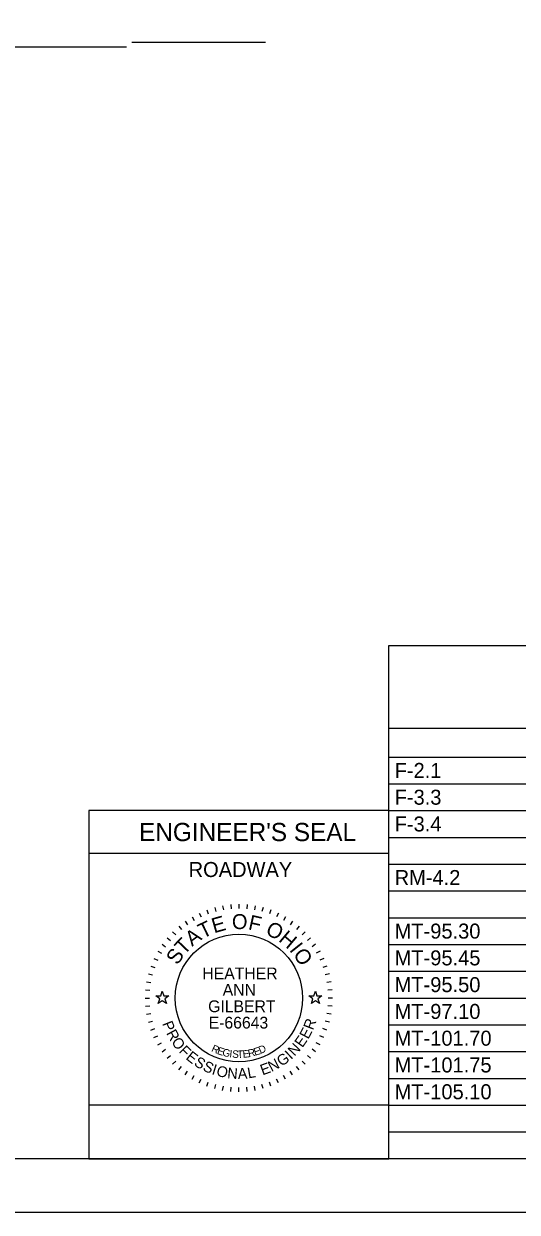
# Model space of a CAD drawing. Extents: x 0 to 34, y 0 to 22.
# Drawn here: x 6.74 to 11.35, y 0 to 11.1 of the extents above; entities that cross this region are included whole.
import ezdxf

# ---------------------------------------------------------------- set-up
doc = ezdxf.new("R2010")
doc.units = 0
for name, color, linetype in [('Default', 7, 'Continuous'), ('SH_Border', 7, 'Continuous'), ('SH_Cut_Line', 7, 'Continuous'), ('SH_Data', 7, 'Continuous'), ('SH_Text', 7, 'Continuous')]:
    doc.layers.add(name, color=color, linetype=linetype)

msp = doc.modelspace()

# ---------------------------------------------------------------- linework, layer by layer
at = {"layer": 'Default'}
for points in [[(7.974, 2.02), (8.021, 2.02), (8.035, 2.065), (8.049, 2.02), (8.096, 2.02), (8.058, 1.992), (8.073, 1.948), (8.035, 1.975), (7.997, 1.948), (8.012, 1.992)], [(9.404, 2.02), (9.451, 2.02), (9.465, 2.065), (9.479, 2.02), (9.526, 2.02), (9.488, 1.992), (9.503, 1.948), (9.465, 1.975), (9.427, 1.948), (9.442, 1.992)]]:
    msp.add_lwpolyline(points, close=True, dxfattribs=at)
at = {"layer": 'SH_Border'}
msp.add_lwpolyline([(1.5, 21.5), (33.5, 21.5), (33.5, 0.5), (1.5, 0.5)], close=True, dxfattribs=at)
at = {"layer": 'SH_Cut_Line'}
msp.add_lwpolyline([(0, 0), (34, 0), (34, 22), (0, 22)], close=True, dxfattribs=at)
at = {"layer": 'SH_Data'}
for p, q in [((7.7, 10.877), (3.347, 10.877)), ((9, 10.922), (7.75, 10.922)), ((10.15, 5.292), (23.6, 5.292)), ((10.15, 0.5), (10.15, 5.292)), ((10.15, 4.521), (23.6, 4.521)), ((10.15, 4.25), (23.6, 4.25)), ((10.15, 4), (23.6, 4)), ((10.15, 3.75), (7.35, 3.75)), ((7.35, 3.75), (7.35, 0.5)), ((10.15, 0.5), (10.15, 3.75)), ((10.15, 3.75), (23.6, 3.75)), ((10.15, 3.5), (23.6, 3.5)), ((10.15, 3.35), (7.35, 3.35)), ((10.15, 3.25), (23.6, 3.25)), ((10.15, 3), (23.6, 3)), ((8.38, 2.793), (8.397, 2.757)), ((8.451, 2.822), (8.464, 2.785)), ((8.524, 2.845), (8.534, 2.807)), ((8.598, 2.862), (8.605, 2.822)), ((8.674, 2.872), (8.677, 2.832)), ((8.75, 2.875), (8.75, 2.835)), ((8.826, 2.872), (8.823, 2.832)), ((8.902, 2.862), (8.895, 2.822)), ((8.976, 2.845), (8.966, 2.807)), ((9.049, 2.822), (9.036, 2.785)), ((9.12, 2.793), (9.103, 2.757)), ((8.188, 2.67), (8.213, 2.64)), ((8.248, 2.717), (8.271, 2.684)), ((8.313, 2.758), (8.333, 2.723)), ((9.187, 2.758), (9.167, 2.723)), ((9.252, 2.717), (9.229, 2.684)), ((9.312, 2.67), (9.287, 2.64)), ((10.15, 2.75), (23.6, 2.75)), ((8.08, 2.562), (8.11, 2.537)), ((8.131, 2.619), (8.16, 2.59)), ((9.369, 2.619), (9.34, 2.59)), ((9.42, 2.562), (9.39, 2.537)), ((8.033, 2.502), (8.066, 2.479)), ((9.467, 2.502), (9.434, 2.479)), ((10.15, 2.5), (23.6, 2.5)), ((7.957, 2.37), (7.993, 2.353)), ((7.992, 2.438), (8.027, 2.418)), ((9.508, 2.438), (9.473, 2.418)), ((9.543, 2.37), (9.507, 2.353)), ((7.905, 2.226), (7.943, 2.216)), ((7.928, 2.299), (7.965, 2.286)), ((9.572, 2.299), (9.535, 2.286)), ((9.595, 2.226), (9.557, 2.216)), ((10.15, 2.25), (23.6, 2.25)), ((7.888, 2.152), (7.928, 2.145)), ((9.612, 2.152), (9.572, 2.145)), ((7.875, 2), (7.915, 2)), ((7.878, 2.076), (7.918, 2.073)), ((9.622, 2.076), (9.582, 2.073)), ((9.625, 2), (9.585, 2)), ((10.15, 2), (23.6, 2)), ((7.878, 1.924), (7.918, 1.927)), ((9.622, 1.924), (9.582, 1.927)), ((7.888, 1.848), (7.928, 1.855)), ((7.905, 1.774), (7.943, 1.784)), ((9.595, 1.774), (9.557, 1.784)), ((9.612, 1.848), (9.572, 1.855)), ((7.928, 1.701), (7.965, 1.714)), ((9.572, 1.701), (9.535, 1.714)), ((10.15, 1.75), (23.6, 1.75)), ((7.957, 1.63), (7.993, 1.647)), ((7.992, 1.563), (8.027, 1.583)), ((9.508, 1.563), (9.473, 1.583)), ((9.543, 1.63), (9.507, 1.647)), ((8.033, 1.498), (8.066, 1.521)), ((8.08, 1.438), (8.11, 1.463)), ((9.42, 1.438), (9.39, 1.463)), ((9.467, 1.498), (9.434, 1.521)), ((10.15, 1.5), (23.6, 1.5)), ((8.131, 1.381), (8.16, 1.41)), ((8.188, 1.33), (8.213, 1.36)), ((9.312, 1.33), (9.287, 1.36)), ((9.369, 1.381), (9.34, 1.41)), ((8.248, 1.283), (8.271, 1.316)), ((8.313, 1.242), (8.333, 1.277)), ((8.38, 1.207), (8.397, 1.243)), ((9.12, 1.207), (9.103, 1.243)), ((9.187, 1.242), (9.167, 1.277)), ((9.252, 1.283), (9.229, 1.316)), ((10.15, 1.25), (23.6, 1.25)), ((8.451, 1.178), (8.464, 1.215)), ((8.524, 1.155), (8.534, 1.193)), ((8.598, 1.138), (8.605, 1.178)), ((8.674, 1.128), (8.677, 1.168)), ((8.75, 1.125), (8.75, 1.165)), ((8.826, 1.128), (8.823, 1.168)), ((8.902, 1.138), (8.895, 1.178)), ((8.976, 1.155), (8.966, 1.193)), ((9.049, 1.178), (9.036, 1.215)), ((10.15, 1), (23.6, 1)), ((10.15, 0.75), (23.6, 0.75)), ((10.15, 0.5), (7.35, 0.5))]:
    msp.add_line(p, q, dxfattribs=at)
msp.add_lwpolyline([(10.15, 0.5), (10.15, 1), (7.35, 1), (7.35, 0.5)], close=True, dxfattribs=at)
msp.add_circle((8.75, 2), 0.595, dxfattribs=at)

# ---------------------------------------------------------------- texts
for s, height, p in [("ENGINEER'S SEAL", 0.17, (7.818, 3.465)), ('ROADWAY', 0.14, (8.281, 3.13)), ('HEATHER ', 0.11, (8.409, 2.175)), ('ANN', 0.11, (8.599, 2.022)), ('GILBERT', 0.11, (8.463, 1.868)), ('E-66643', 0.11, (8.468, 1.715))]:
    msp.add_text(s, height=height, dxfattribs=at).set_placement(p)
for s, height, rotation, p in [('O', 0.14, 359.7812, (8.685, 2.644)), ('F', 0.14, 347.4362, (8.831, 2.642)), ('T', 0.14, 25.7167, (8.412, 2.552)), ('E', 0.14, 15.7571, (8.518, 2.604)), ('O', 0.14, 332.2586, (8.99, 2.602)), ('T', 0.14, 46.4344, (8.238, 2.396)), ('A', 0.14, 36.4747, (8.313, 2.478)), ('H', 0.14, 319.9136, (9.113, 2.536)), ('S', 0.14, 57.1924, (8.178, 2.301)), ('I', 0.14, 308.367, (9.216, 2.448)), ('O', 0.14, 303.1491, (9.252, 2.409)), ('P', 0.1, 291.494, (8.032, 1.762)), ('R', 0.1, 69.2322, (9.442, 1.695)), ('R', 0.1, 298.7311, (8.069, 1.672)), ('E', 0.1, 61.9951, (9.398, 1.61)), ('O', 0.1, 306.4666, (8.115, 1.588)), ('F', 0.1, 314.7068, (8.184, 1.498)), ('R', 0.07, 334.487, (8.487, 1.505)), ('D', 0.07, 23.3052, (8.951, 1.477)), ('N', 0.1, 47.0224, (9.27, 1.451)), ('E', 0.1, 54.758, (9.343, 1.531)), ('E', 0.1, 321.4393, (8.248, 1.435)), ('S', 0.1, 328.6764, (8.324, 1.375)), ('E', 0.07, 341.04, (8.541, 1.48)), ('G', 0.07, 347.4752, (8.591, 1.462)), ('I', 0.07, 353.7858, (8.659, 1.447)), ('S', 0.07, 356.8926, (8.686, 1.443)), ('T', 0.07, 3.0061, (8.736, 1.439)), ('E', 0.07, 6.0117, (8.789, 1.441)), ('R', 0.07, 11.9184, (8.842, 1.447)), ('E', 0.07, 17.6836, (8.9, 1.46)), ('G', 0.1, 35.0469, (9.148, 1.357)), ('I', 0.1, 43.287, (9.237, 1.421)), ('S', 0.1, 335.9134, (8.406, 1.327)), ('I', 0.1, 343.1505, (8.491, 1.29)), ('O', 0.1, 346.8859, (8.534, 1.275)), ('N', 0.1, 355.1261, (8.639, 1.252)), ('A', 0.1, 2.8617, (8.742, 1.244)), ('L', 0.1, 10.0987, (8.839, 1.249)), ('E', 0.1, 20.0742, (8.971, 1.277)), ('N', 0.1, 27.3113, (9.054, 1.308))]:
    msp.add_text(s, height=height, rotation=rotation, dxfattribs=at).set_placement(p)
at = {"layer": 'SH_Text'}
for s, p in [('F-2.1', (10.205, 4.055)), ('F-3.3', (10.205, 3.805)), ('F-3.4', (10.205, 3.555)), ('RM-4.2', (10.205, 3.055)), ('MT-95.30', (10.205, 2.555)), ('MT-95.45', (10.205, 2.305)), ('MT-95.50', (10.205, 2.055)), ('MT-97.10', (10.205, 1.805)), ('MT-101.70', (10.205, 1.555)), ('MT-101.75', (10.205, 1.305)), ('MT-105.10', (10.205, 1.055))]:
    msp.add_text(s, height=0.14, dxfattribs=at).set_placement(p)

doc.saveas('drawing.dxf')
